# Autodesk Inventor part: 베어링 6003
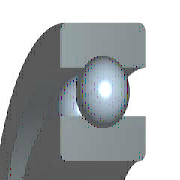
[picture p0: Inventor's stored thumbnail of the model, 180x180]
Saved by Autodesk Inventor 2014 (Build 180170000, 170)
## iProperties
Created: 2012-02
Part Number: 베어링 6003
Material: 강철, 연강
Description: 깊은 그루브 볼 베어링
Document SubType Name: Modeling
Standard: KS B 2023
Designer: mduedu
Standards Organization: KS
Language: ko-KR
Size Designation: 6003 - 17 x 35 x 10
Categories: <MemberInstance><Categories><Category DisplayName="샤프트 부품" InternalName="7f7aeb1f-a693-4053-b835-cee3144e0d98" Mnemonic="SHFT"><Category DisplayName="베어링" Inter
Density: 1 g/cm^3
Appearance: 밝은 황색
IsCustomPart: 1
Author: mduedu
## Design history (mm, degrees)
sketch "스케치" dims "d0" = 4.68 (= -0.26 x WD + 0.26 x BD)
  geometry: L1 (2.66, 13)-(7.34, 13); L2 (5, 13)-(5, 10.66); L3 (5, 13)-(5, 15.34); L4 (3.261, 11.434)-(0, 11.434); L5 (0, 8.5)-(10, 8.5); L6 (3.261, 14.566)-(0, 14.566); L7 (0, 17.5)-(10, 17.5); L8 (10, 8.5)-(10, 11.434); L9 (6.739, 11.434)-(10, 11.434); L10 (6.739, 14.566)-(10, 14.566); L11 (10, 17.5)-(10, 14.566); L12 (-1.4, 0)-(8.4, 0) reference; L13 (0, -0.3)-(0, 5.3) reference
  constraints: 22 end point, 4 point on line, 2 collinear, 2 perpendicular, 2 symmetric about line, 1 midpoint, 1 parallel, 14 other
  dimensions: "d9" = 17 diameter of L5 L12 (= WD); "d11" = 35 diameter of L7 L12 (= BD); "d12" = 10 distance between parallel lines of L8 L13 (= KB); "d13" = 22.868 diameter of L9 L12 (= 0.326 x BD + 0.674 x WD)
revolve "본체" stored, may be unused: angle "d6" = 90 deg
revolve "볼" stored, may be unused: angle "d7" = 90 deg
pattern_circular "IDS_ARRAYBALL[SIMPL:T]" dims angle "d3" = 360 deg
body "Solid1"
fillet "모깎기1" dims "d1" = 0.3 (= KRS)
other parameters: "WD" = 17 [user parameter; used in 5 equation terms], "BD" = 35 [user parameter; used in 5 equation terms], "KB" = 10 [user parameter; used in 1 equation term], "KRS" = 0.3 [user parameter; used in 1 equation term], "d4" = 0, "d5" = 0, "d8" = 0, "d14" = 0, "d15" = 0, "BBA" = 0 [user parameter], "BC0" = 3250000 [user parameter], "BC" = 6050000 [user parameter], "BR" = 17.5 (= 0.5 x BD) [user parameter], "WR" = 8.5 (= 0.5 x WD) [user parameter]
